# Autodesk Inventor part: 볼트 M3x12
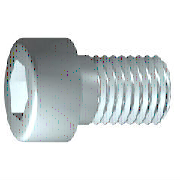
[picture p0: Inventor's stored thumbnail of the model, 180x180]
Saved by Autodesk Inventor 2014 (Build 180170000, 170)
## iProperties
IsCustomPart: 0
Created: 2012-02
Part Number: 볼트 M3x12
Material: 강철, 연강
Description: 6각머리 태핑 나사
Document SubType Name: Modeling
Standard: KS B 1003
Designer: mduedu
Standards Organization: KS
Language: ko-KR
Size Designation: M 3 x 12
Categories: <MemberInstance><Categories><Category DisplayName="조임쇠" InternalName="e4da775c-781d-43d5-af7c-5136215cf5a6" Mnemonic="FSTN"><Category DisplayName="볼트" InternalN
Density: 7.86 g/cm^3
Appearance: 강철
Mass: 1.15208 g
Surface Area: 2.207 cm^2
Volume: 0.146575 cm^3
Author: mduedu
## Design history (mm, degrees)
sketch "스케치1"
  geometry: L1 (-0.867, 0)-(12, 0); L2 (12, 0)-(12, 1.5); L3 (12, 1.5)-(1.25, 1.5); L4 (1.25, 1.5)-(0.943, 1.5); L5 (0.943, 1.5)-(0, 1.5); L6 (0, 1.5)-(0, 2.75); L7 (0, 2.75)-(-3, 2.75); L8 (-3, 2.75)-(-3, 1.443); L9 (-3, 1.443)-(-1.7, 1.443); L10 (-1.7, 1.443)-(-0.867, 0); L11 (-6, 0)-(15, 0) reference; L12 (0, -0.55)-(0, 3.3) reference; L13 (1.25, 1.5)-(0, 1.5)
  constraints: 22 end point, 6 parallel, 2 collinear, 2 perpendicular, 1 horizontal, 1 point on line
  dimensions: "d1" = 10.75 distance from line of L3.end L2 (= GEL); "d2" = 0.30683 distance of L4.end L3.end (computed from GAL); "d3" = 3 distance between parallel lines of L8 L6 (= KOH); "d4" = 1.3 distance of L8.end L9.end (= INTI); "d5" = 60 deg angle of L10 L1; "d6" = 3 diameter of L3 L1 (= GD); "d7" = 3 diameter of L5 L1 (= BDM); "d8" = 2.88675 diameter of L9 L1 (= 1.1547 x SW); "d9" = 5.5 diameter of L7 L1 (= KOD); "d26" = 12 distance between parallel lines of L12 L2 (= NLG)
revolve "본체" sketch "스케치1" stored, may be unused: angle "d10" = 90 deg
sketch "스케치2"
  geometry: L1 (0, -3.85)-(0, 3.85) reference; L2 (-3.85, 0)-(3.85, 0) reference; L3 (1.443, 0)-(0.722, -1.25); L4 (0.722, -1.25)-(-0.722, -1.25); L5 (-0.722, -1.25)-(-1.443, 0); L6 (-1.443, 0)-(-0.722, 1.25); L7 (-0.722, 1.25)-(0.722, 1.25); L8 (0.722, 1.25)-(1.443, 0); 2 further points
  constraints: 12 end point, 1 coincident, 1 horizontal alignment, 1 point on line, 12 other
extrude "슬롯" join sketch "스케치2" stored distance "d11" = 10; taper "d12" = 0 deg
workplane "Work Plane1"
fillet "Fillet2" dims "d30" = 0.1 (= R)
body "Solid1"
fillet "모깎기1" dims "d17" = 0.3 (= RR)
feature "스레드" dims "d13" = 10.75 (= GEL), "d14" = 0
chamfer "모따기1" distance "d15" = 0.30673 (= -0.5 x SPD + 0.5 x GD); stored, may be unused: second distance "d16" = 0.30673 (= GUL), angle "d27" = 45 deg
other parameters: "GD" = 3 (= NND) [user parameter; used in 2 equation terms], "NLG" = 12 [user parameter; used in 1 equation term], "GEL" = 10.75 [user parameter; used in 2 equation terms], "KOD" = 5.5 [user parameter; used in 1 equation term], "KOH" = 3 [user parameter; used in 1 equation term], "INTI" = 1.3 [user parameter; used in 1 equation term], "GAL" = 0.30673 (= 0.61345 x PTC) [user parameter; used in 1 equation term], "GUL" = 0.30673 (= 0.61345 x PTC) [user parameter; used in 1 equation term], "BDM" = 3 (= NND) [user parameter; used in 1 equation term], "SW" = 2.5 [user parameter; used in 2 equation terms], "RR" = 0.3 [user parameter; used in 1 equation term], "SPD" = 2.38655 (= NND - 1.2269 x PTC) [user parameter; used in 1 equation term], "d19" = 0, "d28" = 0, "d29" = 0, "R" = 0.1 [user parameter; used in 1 equation term], "PHH" = 0.1 [user parameter], "GD1" = 2.38655 (= THREADDIA - 1.2269 x PTC) [user parameter], "THREADDIA" = 3 [user parameter; used in 1 equation term], "FAWI" = 45 deg [user parameter], "PTC" = 0.5 [user parameter; used in 5 equation terms], "NND" = 3 [user parameter; used in 3 equation terms], "TOA" = 30 deg [user parameter], "E0" = 2.8875 (= 1.155 x SW) [user parameter]
